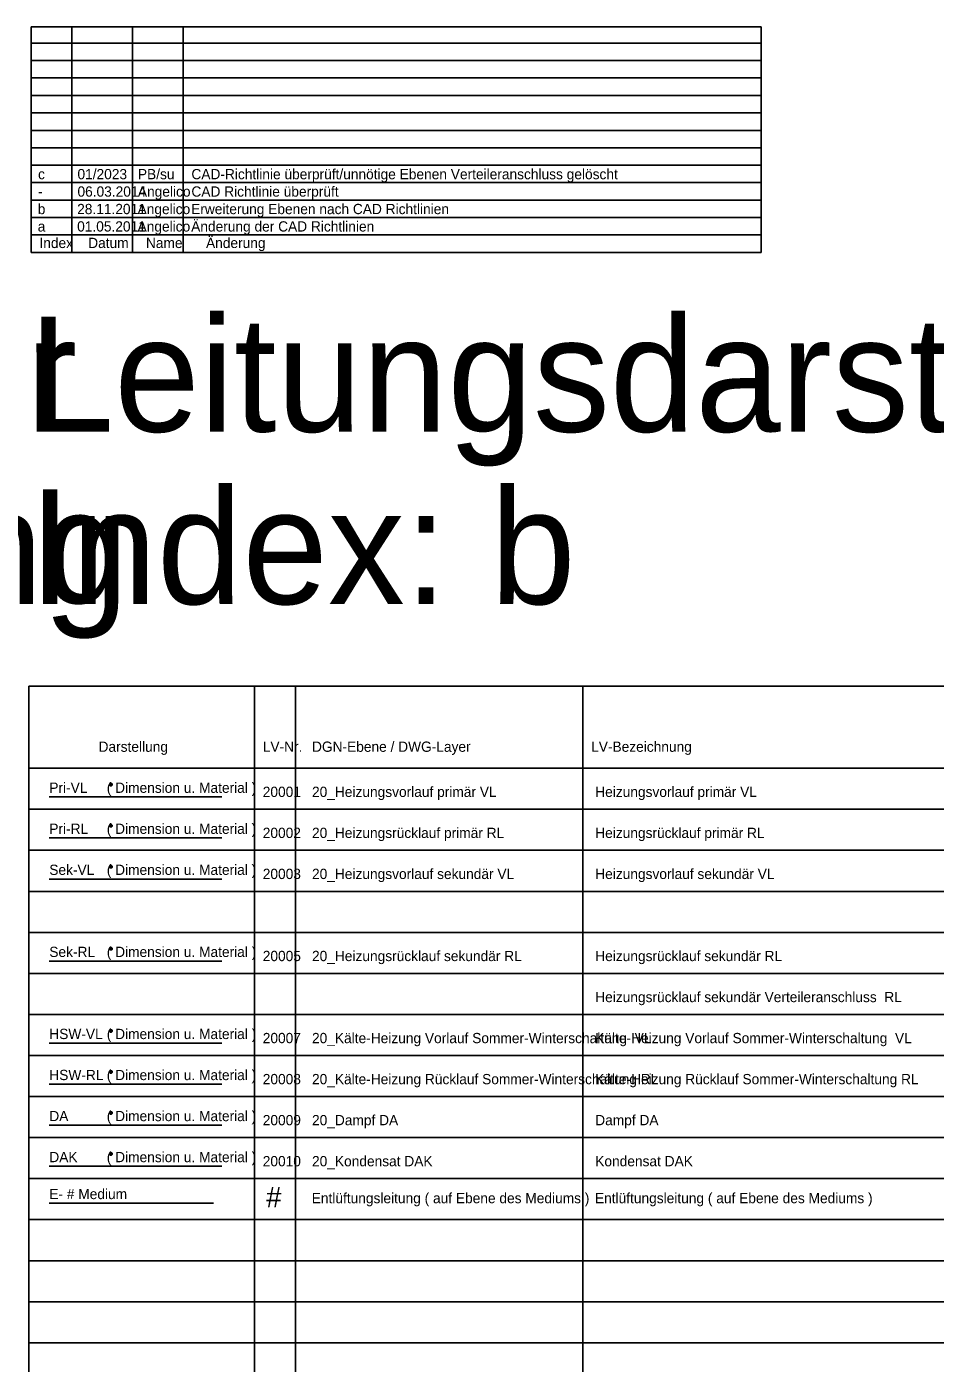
# Model space of a CAD drawing. Extents: x -14.3 to 24, y -56.3 to 8.
# Drawn here: x -0.03 to 11.04, y -8.25 to 8.03 of the extents above; entities that cross this region are included whole.
import ezdxf

# ---------------------------------------------------------------- set-up
doc = ezdxf.new("R2010")
doc.units = 0
for name, color, linetype in [('20_Dampf DA', 7, 'Continuous'), ('20_Heizungsrücklauf primär RL', 7, 'Continuous'), ('20_Heizungsrücklauf sekundär RL', 7, 'Continuous'), ('20_Heizungsvorlauf primär VL', 7, 'Continuous'), ('20_Heizungsvorlauf sekundär VL', 7, 'Continuous'), ('20_Kondensat DAK', 7, 'Continuous'), ('20_Kälte-Heizung Rücklauf Sommer-Winterschaltung RL', 7, 'Continuous'), ('20_Kälte-Heizung Vorlauf Sommer-Winterschaltung  VL', 7, 'Continuous'), ('20_z_freie_Ebene_01', 7, 'Continuous'), ('Default', 7, 'Continuous')]:
    doc.layers.add(name, color=color, linetype=linetype)

msp = doc.modelspace()

# ---------------------------------------------------------------- linework, layer by layer
at = {"layer": '20_Dampf DA'}
for p, q in [((0.978, -5.2), (1.022, -5.2)), ((0.984, -5.184), (1.016, -5.216)), ((1.016, -5.184), (0.984, -5.216)), ((1, -5.178), (1, -5.222)), ((0.25, -5.35), (2.35, -5.35))]:
    msp.add_line(p, q, dxfattribs=at)
at = {"layer": '20_Heizungsrücklauf primär RL'}
for p, q in [((0.978, -1.7), (1.022, -1.7)), ((0.984, -1.684), (1.016, -1.716)), ((1.016, -1.684), (0.984, -1.716)), ((1, -1.678), (1, -1.722)), ((0.25, -1.85), (2.35, -1.85))]:
    msp.add_line(p, q, dxfattribs=at)
at = {"layer": '20_Heizungsrücklauf sekundär RL'}
for p, q in [((0.978, -3.2), (1.022, -3.2)), ((0.984, -3.184), (1.016, -3.216)), ((1.016, -3.184), (0.984, -3.216)), ((1, -3.178), (1, -3.222)), ((0.25, -3.35), (2.35, -3.35))]:
    msp.add_line(p, q, dxfattribs=at)
at = {"layer": '20_Heizungsvorlauf primär VL'}
for p, q in [((0.978, -1.2), (1.022, -1.2)), ((0.984, -1.184), (1.016, -1.216)), ((1.016, -1.184), (0.984, -1.216)), ((1, -1.178), (1, -1.222)), ((0.25, -1.35), (2.35, -1.35))]:
    msp.add_line(p, q, dxfattribs=at)
at = {"layer": '20_Heizungsvorlauf sekundär VL'}
for p, q in [((0.978, -2.2), (1.022, -2.2)), ((0.984, -2.184), (1.016, -2.216)), ((1.016, -2.184), (0.984, -2.216)), ((1, -2.178), (1, -2.222)), ((0.25, -2.35), (2.35, -2.35))]:
    msp.add_line(p, q, dxfattribs=at)
at = {"layer": '20_Kondensat DAK'}
for p, q in [((0.984, -5.684), (1.016, -5.716)), ((1.016, -5.684), (0.984, -5.716)), ((1, -5.678), (1, -5.722)), ((0.25, -5.85), (2.35, -5.85)), ((0.978, -5.7), (1.022, -5.7))]:
    msp.add_line(p, q, dxfattribs=at)
at = {"layer": '20_Kälte-Heizung Rücklauf Sommer-Winterschaltung RL'}
for p, q in [((0.978, -4.7), (1.022, -4.7)), ((0.984, -4.684), (1.016, -4.716)), ((1.016, -4.684), (0.984, -4.716)), ((1, -4.678), (1, -4.722)), ((0.25, -4.85), (2.35, -4.85))]:
    msp.add_line(p, q, dxfattribs=at)
at = {"layer": '20_Kälte-Heizung Vorlauf Sommer-Winterschaltung  VL'}
for p, q in [((0.978, -4.2), (1.022, -4.2)), ((0.984, -4.184), (1.016, -4.216)), ((1.016, -4.184), (0.984, -4.216)), ((1, -4.178), (1, -4.222)), ((0.25, -4.35), (2.35, -4.35))]:
    msp.add_line(p, q, dxfattribs=at)
at = {"layer": '20_z_freie_Ebene_01'}
msp.add_line((0.25, -6.3), (2.25, -6.3), dxfattribs=at)
at = {"layer": 'Default'}
for p, q in [((0.029, 5.285), (0.029, 8.034)), ((0.029, 8.034), (8.923, 8.034)), ((0.523, 5.285), (0.523, 8.034)), ((1.264, 5.285), (1.264, 8.034)), ((1.882, 5.285), (1.882, 8.034)), ((8.923, 5.285), (8.923, 8.034)), ((0.029, 7.835), (8.923, 7.835)), ((0.029, 7.622), (8.923, 7.622)), ((0.029, 7.41), (8.923, 7.41)), ((0.029, 7.197), (8.923, 7.197)), ((0.029, 6.985), (8.923, 6.985)), ((0.029, 6.772), (8.923, 6.772)), ((0.029, 6.56), (8.923, 6.56)), ((0.029, 6.347), (8.923, 6.347)), ((0.029, 6.135), (8.923, 6.135)), ((0.029, 5.922), (8.923, 5.922)), ((0.029, 5.71), (8.923, 5.71)), ((0.029, 5.497), (8.923, 5.497)), ((0.029, 5.285), (8.923, 5.285)), ((0.029, 5.285), (8.923, 5.285)), ((0, 0), (0, -53.5)), ((0, 0), (16, 0)), ((2.75, 0), (2.75, -53.5)), ((3.25, 0), (3.25, -53.5)), ((6.75, 0), (6.75, -53.5)), ((0, -1), (14.169, -1)), ((0, -1), (16, -1)), ((0, -1.5), (16, -1.5)), ((0, -2), (16, -2)), ((0, -2.5), (16, -2.5)), ((0, -3), (16, -3)), ((0, -3.5), (16, -3.5)), ((0, -4), (16, -4)), ((0, -4.5), (16, -4.5)), ((0, -5), (16, -5)), ((0, -5.5), (16, -5.5)), ((0, -6), (16, -6)), ((0, -6.5), (16, -6.5)), ((0, -7), (16, -7)), ((0, -7.5), (16, -7.5)), ((0, -8), (16, -8))]:
    msp.add_line(p, q, dxfattribs=at)

# ---------------------------------------------------------------- texts
at = {"layer": '20_Dampf DA'}
for s, p in [('DA', (0.25, -5.3)), ('( Dimension u. Material )', (0.95, -5.3))]:
    msp.add_text(s, height=0.125, dxfattribs=at).set_placement(p)
at = {"layer": '20_Heizungsrücklauf primär RL'}
for s, p in [('Pri-RL', (0.25, -1.8)), ('( Dimension u. Material )', (0.95, -1.8))]:
    msp.add_text(s, height=0.125, dxfattribs=at).set_placement(p)
at = {"layer": '20_Heizungsrücklauf sekundär RL'}
for s, p in [('Sek-RL', (0.25, -3.3)), ('( Dimension u. Material )', (0.95, -3.3))]:
    msp.add_text(s, height=0.125, dxfattribs=at).set_placement(p)
at = {"layer": '20_Heizungsvorlauf primär VL'}
for s, p in [('Pri-VL', (0.25, -1.3)), ('( Dimension u. Material )', (0.95, -1.3))]:
    msp.add_text(s, height=0.125, dxfattribs=at).set_placement(p)
at = {"layer": '20_Heizungsvorlauf sekundär VL'}
for s, p in [('Sek-VL', (0.25, -2.3)), ('( Dimension u. Material )', (0.95, -2.3))]:
    msp.add_text(s, height=0.125, dxfattribs=at).set_placement(p)
at = {"layer": '20_Kondensat DAK'}
for s, p in [('DAK', (0.25, -5.8)), ('( Dimension u. Material )', (0.95, -5.8))]:
    msp.add_text(s, height=0.125, dxfattribs=at).set_placement(p)
at = {"layer": '20_Kälte-Heizung Rücklauf Sommer-Winterschaltung RL'}
for s, p in [('HSW-RL', (0.25, -4.8)), ('( Dimension u. Material )', (0.95, -4.8))]:
    msp.add_text(s, height=0.125, dxfattribs=at).set_placement(p)
at = {"layer": '20_Kälte-Heizung Vorlauf Sommer-Winterschaltung  VL'}
for s, p in [('HSW-VL', (0.25, -4.3)), ('( Dimension u. Material )', (0.95, -4.3))]:
    msp.add_text(s, height=0.125, dxfattribs=at).set_placement(p)
at = {"layer": '20_z_freie_Ebene_01'}
msp.add_text('E- # Medium', height=0.125, dxfattribs=at).set_placement((0.25, -6.25))
at = {"layer": 'Default'}
for s, height, p in [('c     ', 0.125, (0.113, 6.176)), ('01/2023   ', 0.125, (0.593, 6.176)), ('PB/su   ', 0.125, (1.329, 6.176)), ('CAD-Richtlinie überprüft/unnötige Ebenen Verteileranschluss gelöscht                            ', 0.125, (1.981, 6.176)), ('06.03.2014', 0.125, (0.593, 5.964)), ('Angelico', 0.125, (1.329, 5.964)), ('CAD Richtlinie überprüft                                                                        ', 0.125, (1.981, 5.964)), ('b     ', 0.125, (0.109, 5.751)), ('-     ', 0.125, (0.113, 5.964)), ('28.11.2011', 0.125, (0.589, 5.751)), ('Angelico', 0.125, (1.325, 5.751)), ('Erweiterung Ebenen nach CAD Richtlinien                                                         ', 0.125, (1.978, 5.751)), ('a     ', 0.125, (0.109, 5.539)), ('01.05.2011', 0.125, (0.589, 5.539)), ('Angelico', 0.125, (1.325, 5.539)), ('Änderung der CAD Richtlinien                                                                    ', 0.125, (1.978, 5.539)), ('Index', 0.125, (0.13, 5.338)), ('Datum', 0.125, (0.724, 5.338)), ('Name', 0.125, (1.427, 5.338)), ('Änderung', 0.125, (2.159, 5.338)), ('Musterlegende für ', 1.4, (-14.5, 3.1)), ('Leitungsdarstellung: Heizung ', 1.4, (0, 3.1)), ('Blattpläne Heizung', 1.4, (-14.5, 1)), ('Index: b', 1.4, (0, 1)), ('Darstellung', 0.125, (0.85, -0.8)), ('LV-Nr.', 0.125, (2.85, -0.8)), ('DGN-Ebene / DWG-Layer', 0.125, (3.45, -0.8)), ('LV-Bezeichnung', 0.125, (6.85, -0.8)), ('20001', 0.125, (2.85, -1.35)), ('20_Heizungsvorlauf primär VL', 0.125, (3.45, -1.35)), ('Heizungsvorlauf primär VL', 0.125, (6.9, -1.35)), ('20002', 0.125, (2.85, -1.85)), ('20_Heizungsrücklauf primär RL', 0.125, (3.45, -1.85)), ('Heizungsrücklauf primär RL', 0.125, (6.9, -1.85)), ('20003', 0.125, (2.85, -2.35)), ('20_Heizungsvorlauf sekundär VL', 0.125, (3.45, -2.35)), ('Heizungsvorlauf sekundär VL', 0.125, (6.9, -2.35)), ('20005', 0.125, (2.85, -3.35)), ('20_Heizungsrücklauf sekundär RL', 0.125, (3.45, -3.35)), ('Heizungsrücklauf sekundär RL', 0.125, (6.9, -3.35)), ('Heizungsrücklauf sekundär Verteileranschluss  RL', 0.125, (6.9, -3.85)), ('20007', 0.125, (2.85, -4.35)), ('20_Kälte-Heizung Vorlauf Sommer-Winterschaltung  VL', 0.125, (3.45, -4.35)), ('Kälte-Heizung Vorlauf Sommer-Winterschaltung  VL', 0.125, (6.9, -4.35)), ('20_Kälte-Heizung Rücklauf Sommer-Winterschaltung RL', 0.125, (3.45, -4.85)), ('Kälte-Heizung Rücklauf Sommer-Winterschaltung RL', 0.125, (6.9, -4.85)), ('20008', 0.125, (2.85, -4.85)), ('20009', 0.125, (2.85, -5.35)), ('20_Dampf DA', 0.125, (3.45, -5.35)), ('Dampf DA', 0.125, (6.9, -5.35)), ('20010', 0.125, (2.85, -5.85)), ('20_Kondensat DAK', 0.125, (3.45, -5.85)), ('Kondensat DAK', 0.125, (6.9, -5.85)), (' # ', 0.25, (2.8, -6.35)), (' Entlüftungsleitung ( auf Ebene des Mediums )', 0.125, (3.4, -6.3)), (' Entlüftungsleitung ( auf Ebene des Mediums )', 0.125, (6.85, -6.3))]:
    msp.add_text(s, height=height, dxfattribs=at).set_placement(p)

doc.saveas('drawing.dxf')
